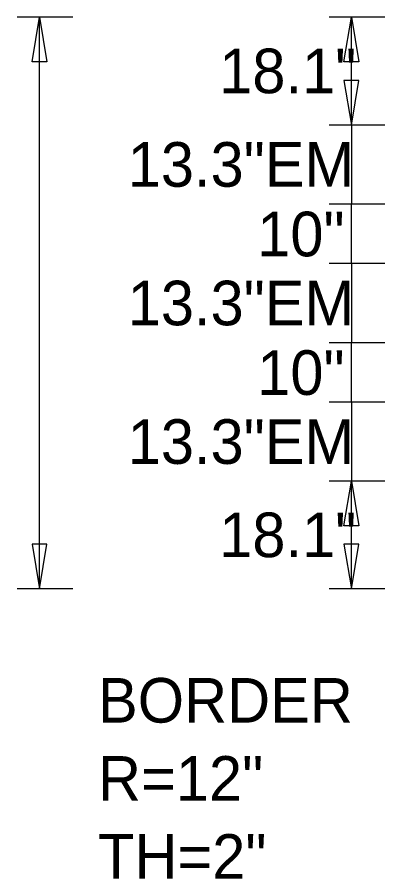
# Model space of a CAD drawing. Extents: x 1806251 to 1809821, y 414895 to 422886.
# Drawn here: x 1809675.84 to 1809676.458, y 415091.413 to 415092.861 of the extents above; entities that cross this region are included whole.
import ezdxf

# ---------------------------------------------------------------- set-up
doc = ezdxf.new("R2010")
doc.units = 0
doc.layers.add('GSDIMS', color=7, linetype='Continuous')

msp = doc.modelspace()

# ---------------------------------------------------------------- linework, layer by layer
at = {"layer": 'GSDIMS'}
for p, q in [((1809675.9333, 415092.8611), (1809675.8396, 415092.8611)), ((1809675.8771, 415091.9001), (1809675.8771, 415092.8611)), ((1809676.4583, 415092.8611), (1809676.3646, 415092.8611)), ((1809676.4021, 415092.6798), (1809676.4021, 415092.8611)), ((1809676.4583, 415092.6798), (1809676.3646, 415092.6798)), ((1809676.4583, 415092.6798), (1809676.3646, 415092.6798)), ((1809676.4021, 415092.6798), (1809676.4021, 415092.5468)), ((1809676.4583, 415092.5468), (1809676.3646, 415092.5468)), ((1809676.4583, 415092.5468), (1809676.3646, 415092.5468)), ((1809676.4021, 415092.4468), (1809676.4021, 415092.5468)), ((1809676.4583, 415092.4468), (1809676.3646, 415092.4468)), ((1809676.4583, 415092.4468), (1809676.3646, 415092.4468)), ((1809676.4021, 415092.4468), (1809676.4021, 415092.3138)), ((1809676.4583, 415092.3138), (1809676.3646, 415092.3138)), ((1809676.4583, 415092.3138), (1809676.3646, 415092.3138)), ((1809676.4021, 415092.2138), (1809676.4021, 415092.3138)), ((1809676.4583, 415092.2138), (1809676.3646, 415092.2138)), ((1809676.4583, 415092.2138), (1809676.3646, 415092.2138)), ((1809676.4021, 415092.2138), (1809676.4021, 415092.0808)), ((1809676.4583, 415092.0808), (1809676.3646, 415092.0808)), ((1809676.4583, 415092.0808), (1809676.3646, 415092.0808)), ((1809676.4021, 415091.9001), (1809676.4021, 415092.0808)), ((1809675.9333, 415091.9001), (1809675.8396, 415091.9001)), ((1809676.4583, 415091.9001), (1809676.3646, 415091.9001))]:
    msp.add_line(p, q, dxfattribs=at)
for points in [[(1809675.8771, 415092.8611), (1809675.8896, 415092.7861), (1809675.8646, 415092.7861)], [(1809676.4021, 415092.8611), (1809676.4146, 415092.7861), (1809676.3896, 415092.7861)], [(1809676.4021, 415092.6798), (1809676.4146, 415092.7548), (1809676.3896, 415092.7548)], [(1809676.4021, 415092.0808), (1809676.4146, 415092.0058), (1809676.3896, 415092.0058)], [(1809675.8771, 415091.9001), (1809675.8896, 415091.9751), (1809675.8646, 415091.9751)], [(1809676.4021, 415091.9001), (1809676.4146, 415091.9751), (1809676.3896, 415091.9751)]]:
    msp.add_lwpolyline(points, close=True, dxfattribs=at)

# ---------------------------------------------------------------- texts
for s, p in [('18.1"', (1809676.1796, 415092.7333)), ('13.3"EM', (1809676.0256, 415092.5761)), ('10"', (1809676.2436, 415092.4591)), ('13.3"EM', (1809676.0256, 415092.3431)), ('10"', (1809676.2436, 415092.2261)), ('13.3"EM', (1809676.0256, 415092.1101)), ('18.1"', (1809676.1796, 415091.9533)), ('BORDER', (1809675.9756, 415091.6751)), ('R=12"', (1809675.9756, 415091.5438)), ('TH=2"', (1809675.9756, 415091.4126))]:
    msp.add_text(s, height=0.075, dxfattribs=at).set_placement(p)

doc.saveas('drawing.dxf')
